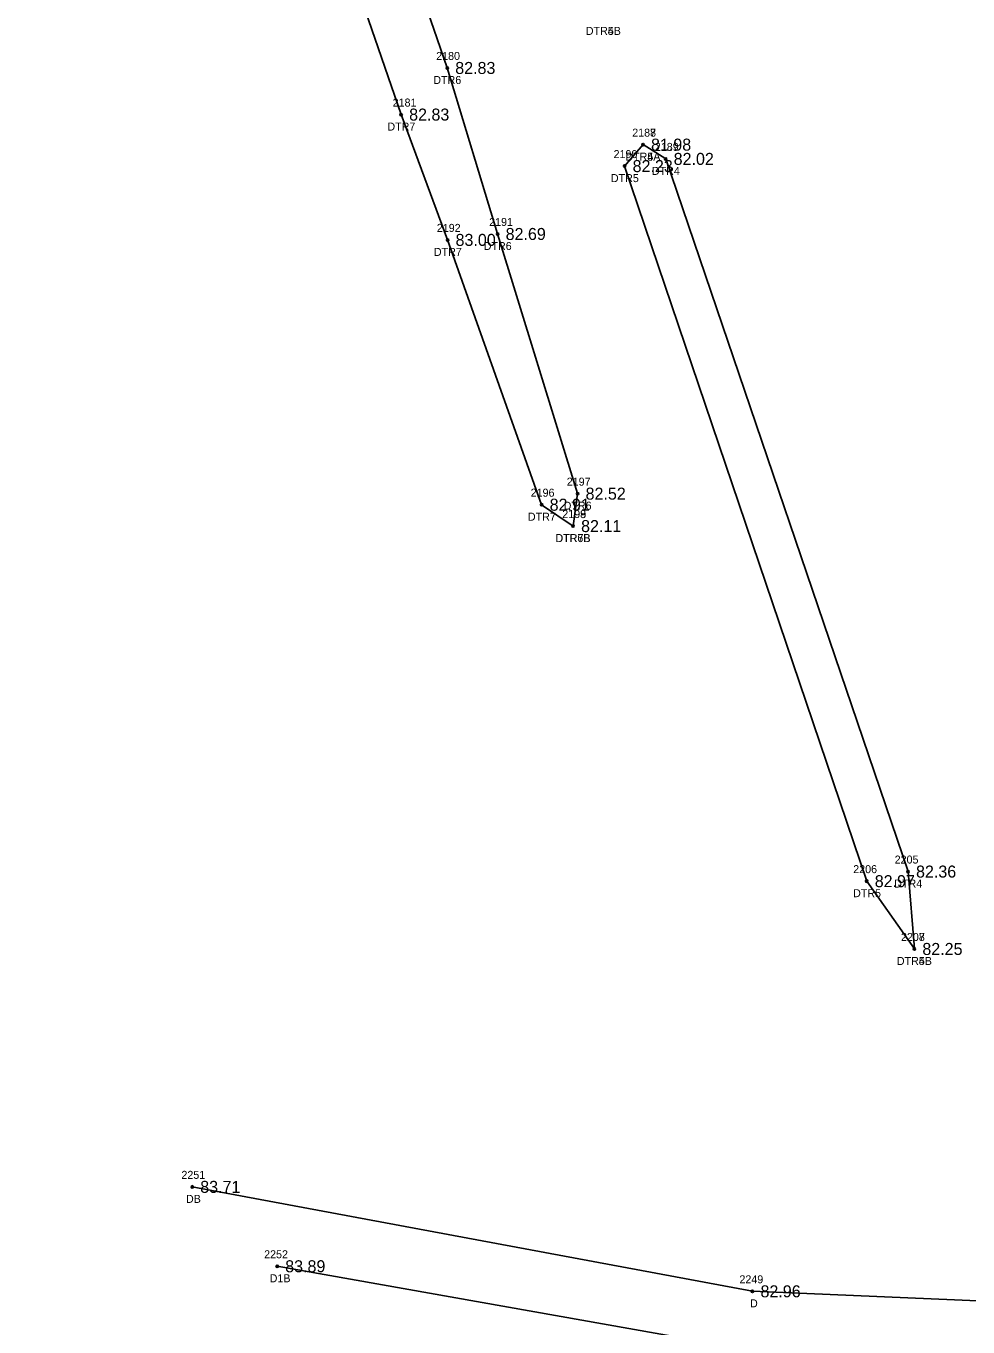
# Model space of a CAD drawing. Extents: x 2139392 to 2143384, y 505395 to 510520.
# Drawn here: x 2140403.2 to 2140521, y 507173.4 to 507335.9 of the extents above; entities that cross this region are included whole.
import ezdxf

# ---------------------------------------------------------------- set-up
doc = ezdxf.new("R2010")
doc.units = 0
for name, color, linetype in [('RD_EX_Driveway', 7, 'Continuous'), ('RD_EX_Driveway_txCode', 7, 'Continuous'), ('RD_EX_H2O', 7, 'Continuous'), ('RD_EX_H2O_txCode', 7, 'Continuous'), ('RD_EX_TX_Driveway_ELEV', 7, 'Continuous'), ('RD_EX_TX_H2O_ELEV', 7, 'Continuous'), ('RD_SMD_Locator', 7, 'Continuous')]:
    doc.layers.add(name, color=color, linetype=linetype)

msp = doc.modelspace()

# ---------------------------------------------------------------- linework, layer by layer
at = {"layer": 'RD_EX_Driveway'}
for points in [[(2140577.5, 507174.26), (2140494.03, 507177.83), (2140424.01, 507190.88)], [(2140577.51, 507165.5), (2140491.76, 507170.87), (2140434.63, 507180.96)]]:
    msp.add_lwpolyline(points, dxfattribs=at)
at = {"layer": 'RD_EX_H2O'}
for points in [[(2140430.62, 507649.52), (2140427.22, 507648.51), (2140403.44, 507549.8), (2140403.24, 507488.1), (2140417.85, 507418.42), (2140450.12, 507324.84), (2140455.92, 507309.18), (2140467.68, 507276.1), (2140471.61, 507273.43)], [(2140430.62, 507649.52), (2140430.5, 507648.1), (2140409.43, 507549.41), (2140409.91, 507490.22), (2140425.46, 507418.84), (2140455.88, 507330.66), (2140462.18, 507309.92), (2140472.17, 507277.48), (2140471.61, 507273.43)], [(2140480.35, 507321.08), (2140478.05, 507318.4), (2140508.31, 507229.07), (2140514.26, 507220.6)], [(2140480.35, 507321.08), (2140483.18, 507319.3), (2140513.47, 507230.27), (2140514.26, 507220.6)]]:
    msp.add_lwpolyline(points, dxfattribs=at)
at = {"layer": 'RD_SMD_Locator'}
for centre in [(2140455.88, 507330.66), (2140450.12, 507324.84), (2140480.35, 507321.08), (2140480.35, 507321.08), (2140478.05, 507318.4), (2140483.18, 507319.3), (2140455.92, 507309.18), (2140462.18, 507309.92), (2140472.17, 507277.48), (2140467.68, 507276.1), (2140471.61, 507273.43), (2140471.61, 507273.43), (2140508.31, 507229.07), (2140513.47, 507230.27), (2140514.26, 507220.6), (2140514.26, 507220.6), (2140424.01, 507190.88), (2140434.63, 507180.96), (2140494.03, 507177.83)]:
    msp.add_circle(centre, 0.15, dxfattribs=at)

# ---------------------------------------------------------------- texts
at = {"layer": 'RD_EX_Driveway_txCode'}
for s, p in [('2251', (2140422.66, 507191.88)), ('DB', (2140423.23, 507188.88)), ('2252', (2140433, 507181.96)), ('D1B', (2140433.69, 507178.96)), ('2249', (2140492.4, 507178.83)), ('D', (2140493.72, 507175.83))]:
    msp.add_text(s, height=1, dxfattribs=at).set_placement(p)
at = {"layer": 'RD_EX_H2O_txCode'}
for s, p in [('DTR4B', (2140473.2, 507334.79)), ('DTR5B', (2140473.2, 507334.79)), ('2180', (2140454.5, 507331.66)), ('DTR6', (2140454.14, 507328.66)), ('2181', (2140449.06, 507325.84)), ('DTR7', (2140448.4, 507322.84)), ('2187', (2140479, 507322.08)), ('2188', (2140479, 507322.08)), ('2190', (2140476.67, 507319.4)), ('DTR4A', (2140478.14, 507319.08)), ('DTR5A', (2140478.14, 507319.08)), ('2189', (2140481.83, 507320.3)), ('DTR4', (2140481.46, 507317.3)), ('DTR5', (2140476.33, 507316.4)), ('2191', (2140461.12, 507310.92)), ('2192', (2140454.58, 507310.18)), ('DTR6', (2140460.44, 507307.92)), ('DTR7', (2140454.21, 507307.18)), ('2197', (2140470.82, 507278.48)), ('2196', (2140466.31, 507277.1)), ('DTR6', (2140470.43, 507275.48)), ('DTR7', (2140465.96, 507274.1)), ('2198', (2140470.26, 507274.43)), ('2199', (2140470.26, 507274.43)), ('DTR6B', (2140469.39, 507271.43)), ('DTR7B', (2140469.42, 507271.43)), ('2205', (2140511.8, 507231.27)), ('2206', (2140506.62, 507230.07)), ('DTR4', (2140511.75, 507228.27)), ('DTR5', (2140506.6, 507227.07)), ('2207', (2140512.59, 507221.6)), ('2208', (2140512.59, 507221.6)), ('DTR5B', (2140512.07, 507218.6)), ('DTR4B', (2140512.07, 507218.6))]:
    msp.add_text(s, height=1, dxfattribs=at).set_placement(p)
at = {"layer": 'RD_EX_TX_Driveway_ELEV'}
for s, p in [('83.71', (2140425.01, 507190.13)), ('83.89', (2140435.63, 507180.21)), ('82.96', (2140495.03, 507177.08))]:
    msp.add_text(s, height=1.5, dxfattribs=at).set_placement(p)
at = {"layer": 'RD_EX_TX_H2O_ELEV'}
for s, p in [('82.83', (2140456.88, 507329.91)), ('82.83', (2140451.12, 507324.09)), ('81.98', (2140481.35, 507320.33)), ('81.98', (2140481.35, 507320.33)), ('82.02', (2140484.18, 507318.55)), ('82.23', (2140479.05, 507317.65)), ('82.69', (2140463.18, 507309.17)), ('83.00', (2140456.92, 507308.43)), ('82.52', (2140473.17, 507276.73)), ('82.91', (2140468.68, 507275.35)), ('82.11', (2140472.61, 507272.68)), ('82.11', (2140472.61, 507272.68)), ('82.36', (2140514.47, 507229.52)), ('82.97', (2140509.31, 507228.32)), ('82.25', (2140515.26, 507219.85)), ('82.25', (2140515.26, 507219.85))]:
    msp.add_text(s, height=1.5, dxfattribs=at).set_placement(p)

doc.saveas('drawing.dxf')
